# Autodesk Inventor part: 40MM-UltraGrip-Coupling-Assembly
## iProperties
Created: 2012-05
Part Number: 40MM-UltraGrip-Coupling-Assembly
Document SubType Name: Modeling
Designer: D Cole
Density: 1 g/cm^3
Author: D Cole
